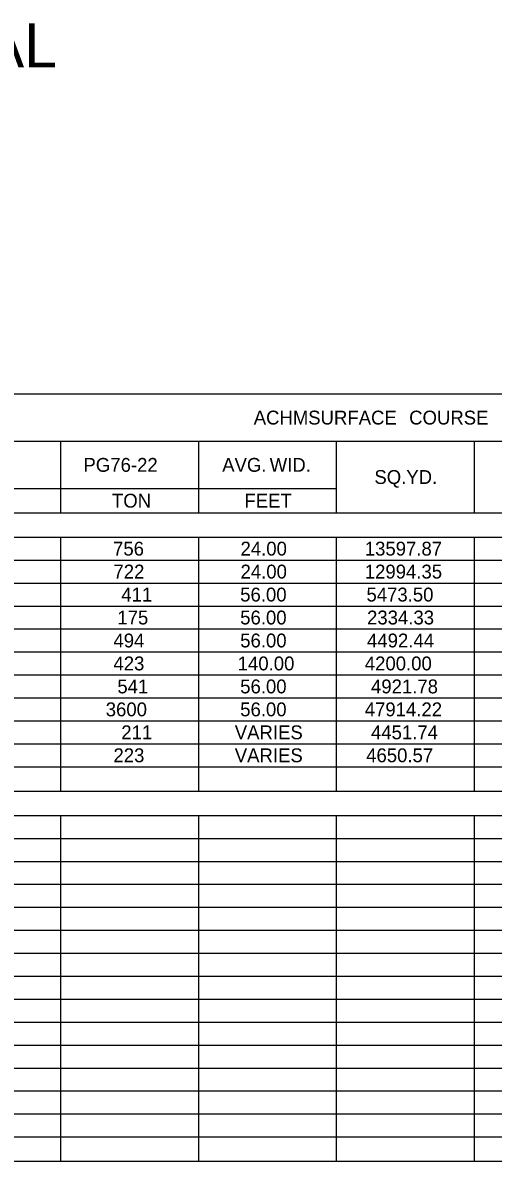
# Model space of a CAD drawing. Extents: x 1226590 to 1228573, y 151304 to 154224.
# Drawn here: x 1227748.5 to 1227882.1, y 151964.1 to 152287.5 of the extents above; entities that cross this region are included whole.
import ezdxf

# ---------------------------------------------------------------- set-up
doc = ezdxf.new("R2010")
doc.units = 0
doc.layers.add('R_Border PE', color=7, linetype='Continuous')
doc.layers.add('R_Dimension', color=7, linetype='Continuous')

msp = doc.modelspace()

# ---------------------------------------------------------------- linework, layer by layer
at = {"layer": 'R_Dimension'}
for p, q in [((1226590.27, 152182.03), (1228150.73, 152182.03)), ((1226898.37, 152168.6), (1228150.73, 152168.6)), ((1227759.37, 152148.27), (1227759.37, 152168.6)), ((1227798.5, 152148.27), (1227798.5, 152168.6)), ((1227837.64, 152148.27), (1227837.64, 152168.6)), ((1227876.78, 152148.27), (1227876.78, 152168.6)), ((1227720.23, 152155.17), (1227837.64, 152155.17)), ((1226590.27, 152148.27), (1228150.73, 152148.27)), ((1227641.96, 152148.27), (1227876.78, 152148.27)), ((1227837.64, 152148.27), (1228150.73, 152148.27)), ((1226590.27, 152141.36), (1228150.73, 152141.36)), ((1227759.37, 152069.23), (1227759.37, 152141.36)), ((1227798.5, 152069.23), (1227798.5, 152141.36)), ((1227837.64, 152069.23), (1227837.64, 152141.36)), ((1227876.78, 152069.23), (1227876.78, 152141.36)), ((1226590.27, 152134.84), (1228150.73, 152134.84)), ((1226590.27, 152128.31), (1228150.73, 152128.31)), ((1226590.27, 152121.79), (1228150.73, 152121.79)), ((1226590.27, 152115.27), (1228150.73, 152115.27)), ((1226590.27, 152108.75), (1228150.73, 152108.75)), ((1226590.27, 152102.22), (1228150.73, 152102.22)), ((1226590.27, 152095.7), (1228150.73, 152095.7)), ((1226590.27, 152089.18), (1228150.73, 152089.18)), ((1226590.27, 152082.65), (1228150.73, 152082.65)), ((1226590.27, 152076.13), (1228150.73, 152076.13)), ((1226590.27, 152069.23), (1228150.73, 152069.23)), ((1226590.27, 152062.32), (1228150.73, 152062.32)), ((1227759.37, 151964.1), (1227759.37, 152062.32)), ((1227798.5, 151964.1), (1227798.5, 152062.32)), ((1227837.64, 151964.1), (1227837.64, 152062.32)), ((1227876.78, 151964.1), (1227876.78, 152062.32)), ((1226590.27, 152055.8), (1228150.73, 152055.8)), ((1226590.27, 152049.27), (1228150.73, 152049.27)), ((1226590.27, 152042.75), (1228150.73, 152042.75)), ((1226590.27, 152036.23), (1228150.73, 152036.23)), ((1226590.27, 152029.71), (1228150.73, 152029.71)), ((1226590.27, 152023.18), (1228150.73, 152023.18)), ((1226590.27, 152016.66), (1228150.73, 152016.66)), ((1226590.27, 152010.14), (1228150.73, 152010.14)), ((1226590.27, 152003.61), (1228150.73, 152003.61)), ((1226590.27, 151997.09), (1228150.73, 151997.09)), ((1226590.27, 151990.57), (1228150.73, 151990.57)), ((1226590.27, 151984.05), (1228150.73, 151984.05)), ((1226590.27, 151977.52), (1228150.73, 151977.52)), ((1226590.27, 151971), (1228150.73, 151971)), ((1226590.27, 151964.1), (1228150.73, 151964.1))]:
    msp.add_line(p, q, dxfattribs=at)

# ---------------------------------------------------------------- texts
at = {"layer": 'R_Border PE'}
msp.add_text('PROFESSIONAL', height=12.4999, dxfattribs=at).set_placement((1227628.2, 152274.78))
at = {"layer": 'R_Dimension'}
for s, p in [('ACHM', (1227814.12, 152173.35)), (' SURFACE', (1227828.13, 152173.35)), (' COURSE', (1227856.79, 152173.35)), ('PG', (1227765.77, 152159.92)), (' 76-22', (1227771.93, 152159.92)), ('AVG.', (1227805.17, 152159.92)), (' WID.', (1227817.19, 152159.92)), ('SQ.YD.', (1227848.38, 152156.47)), ('TON', (1227773.87, 152149.75)), ('FEET', (1227811.49, 152149.75)), ('756', (1227774.18, 152136.13)), ('24.00', (1227810.37, 152136.13)), ('13597.87', (1227845.65, 152136.13)), ('722', (1227774.29, 152129.61)), ('24.00', (1227810.37, 152129.61)), ('12994.35', (1227845.65, 152129.61)), ('411', (1227776.52, 152123.08)), ('56.00', (1227810.28, 152123.08)), ('5473.50', (1227846.13, 152123.08)), ('175', (1227775.4, 152116.56)), ('56.00', (1227810.28, 152116.56)), ('2334.33', (1227846.3, 152116.56)), ('494', (1227774.29, 152110.04)), ('56.00', (1227810.28, 152110.04)), ('4492.44', (1227846.3, 152110.04)), ('423', (1227774.29, 152103.52)), ('140.00', (1227809.57, 152103.52)), ('4200.00', (1227845.66, 152103.52)), ('541', (1227775.4, 152096.99)), ('56.00', (1227810.28, 152096.99)), ('4921.78', (1227847.42, 152096.99)), ('3600', (1227772.1, 152090.47)), ('56.00', (1227810.28, 152090.47)), ('47914.22', (1227845.65, 152090.47)), ('211', (1227776.52, 152083.95)), ('VARIES', (1227808.74, 152083.95)), ('4451.74', (1227847.42, 152083.95)), ('223', (1227774.29, 152077.43)), ('VARIES', (1227808.74, 152077.43)), ('4650.57', (1227846.05, 152077.43))]:
    msp.add_text(s, height=3.935, dxfattribs=at).set_placement(p)

doc.saveas('drawing.dxf')
